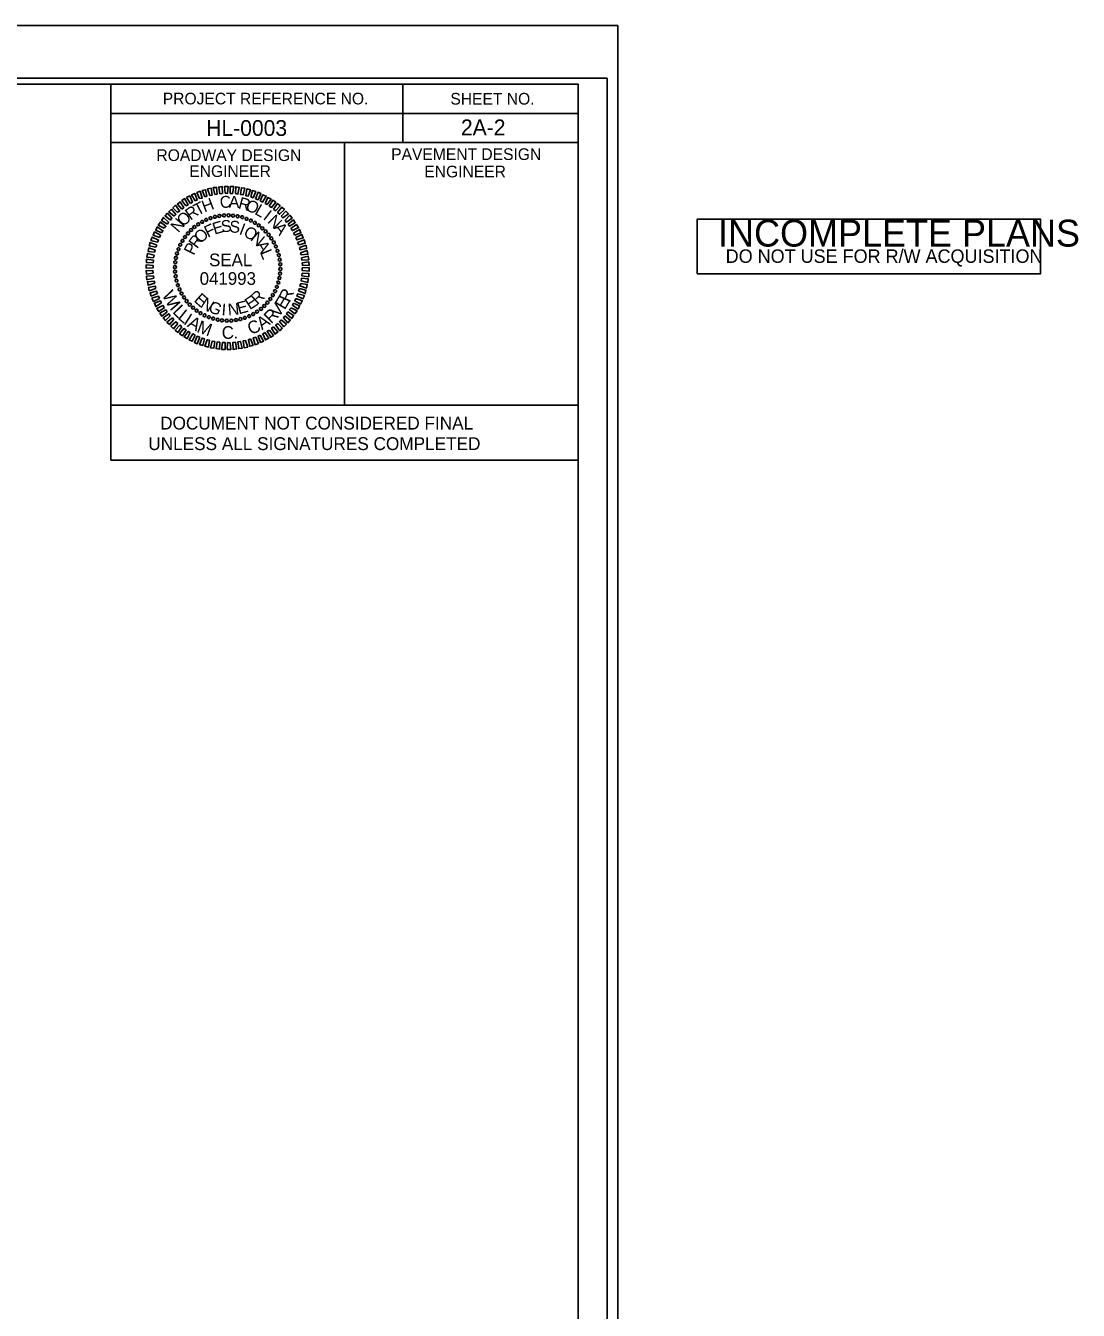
# Model space of a CAD drawing. Extents: x 1022283 to 1026986, y 174822 to 180471.
# Drawn here: x 1025859 to 1026986, y 176197 to 177572 of the extents above; entities that cross this region are included whole.
import ezdxf

# ---------------------------------------------------------------- set-up
doc = ezdxf.new("R2010")
doc.units = 0
for name, color, linetype in [('Default', 7, 'Continuous'), ('Sheet Cutting Line CELL', 7, 'Continuous'), ('Sheet Data Field CELL', 7, 'Continuous'), ('Sheet Plot Border Inside CELL', 7, 'Continuous'), ('Sheet Plot Border Outside CELL', 7, 'Continuous'), ('Sheet Sticker Exception Certification CELL', 7, 'Continuous'), ('Sheet Sticker Incomplete CELL', 7, 'Continuous'), ('Sheet Typical CELL', 7, 'Continuous')]:
    doc.layers.add(name, color=color, linetype=linetype)

msp = doc.modelspace()

# ---------------------------------------------------------------- linework, layer by layer
at = {"layer": 'Default'}
for p, q in [((1026048.2, 177362.5), (1026048.2, 177362.5)), ((1026052.6, 177364.8), (1026052.6, 177364.8)), ((1026057.1, 177366.6), (1026057.1, 177366.6)), ((1026061.8, 177367.9), (1026061.8, 177367.9)), ((1026066.8, 177368.8), (1026066.8, 177368.8)), ((1026071.6, 177369.5), (1026071.6, 177369.5)), ((1026076.6, 177369.6), (1026076.6, 177369.6)), ((1026081.5, 177369.3), (1026081.5, 177369.3)), ((1026086.3, 177368.5), (1026086.3, 177368.5)), ((1026091.1, 177367.5), (1026091.1, 177367.5)), ((1026095.8, 177365.9), (1026095.8, 177365.9)), ((1026100.3, 177363.9), (1026100.3, 177363.9)), ((1026104.7, 177361.6), (1026104.7, 177361.6)), ((1026032.9, 177350.2), (1026032.9, 177350.2)), ((1026036.3, 177353.7), (1026036.3, 177353.7)), ((1026040, 177357.1), (1026040, 177357.1)), ((1026043.9, 177359.9), (1026043.9, 177359.9)), ((1026108.7, 177358.8), (1026108.7, 177358.8)), ((1026112.7, 177355.8), (1026112.7, 177355.8)), ((1026116.2, 177352.4), (1026116.2, 177352.4)), ((1026119.5, 177348.7), (1026119.5, 177348.7)), ((1026024.8, 177337.9), (1026024.8, 177337.9)), ((1026027.1, 177342.3), (1026027.1, 177342.3)), ((1026029.9, 177346.3), (1026029.9, 177346.3)), ((1026122.3, 177344.7), (1026122.3, 177344.7)), ((1026124.9, 177340.5), (1026124.9, 177340.5)), ((1026127.2, 177336.1), (1026127.2, 177336.1)), ((1026020.2, 177323.9), (1026020.2, 177323.9)), ((1026021.2, 177328.6), (1026021.2, 177328.6)), ((1026022.8, 177333.4), (1026022.8, 177333.4)), ((1026129, 177331.6), (1026129, 177331.6)), ((1026130.3, 177326.8), (1026130.3, 177326.8)), ((1026131.2, 177321.9), (1026131.2, 177321.9)), ((1026019.1, 177314.1), (1026019.1, 177314.1)), ((1026019.2, 177309.2), (1026019.2, 177309.2)), ((1026019.4, 177319.1), (1026019.4, 177319.1)), ((1026075.5, 177313.1), (1026075.5, 177313.1)), ((1026131.7, 177307.2), (1026131.7, 177307.2)), ((1026131.9, 177317.1), (1026131.9, 177317.1)), ((1026132, 177312.1), (1026132, 177312.1)), ((1026019.9, 177304.3), (1026019.9, 177304.3)), ((1026020.8, 177299.4), (1026020.8, 177299.4)), ((1026022.1, 177294.7), (1026022.1, 177294.7)), ((1026128.3, 177292.9), (1026128.3, 177292.9)), ((1026129.9, 177297.6), (1026129.9, 177297.6)), ((1026130.9, 177302.3), (1026130.9, 177302.3)), ((1026023.9, 177290.2), (1026023.9, 177290.2)), ((1026026.2, 177285.8), (1026026.2, 177285.8)), ((1026028.7, 177281.5), (1026028.7, 177281.5)), ((1026121.2, 177279.9), (1026121.2, 177279.9)), ((1026124, 177284), (1026124, 177284)), ((1026126.3, 177288.4), (1026126.3, 177288.4)), ((1026031.6, 177277.6), (1026031.6, 177277.6)), ((1026034.9, 177273.9), (1026034.9, 177273.9)), ((1026038.4, 177270.5), (1026038.4, 177270.5)), ((1026042.4, 177267.4), (1026042.4, 177267.4)), ((1026107.2, 177266.3), (1026107.2, 177266.3)), ((1026111.1, 177269.1), (1026111.1, 177269.1)), ((1026114.8, 177272.5), (1026114.8, 177272.5)), ((1026118.2, 177276), (1026118.2, 177276)), ((1026046.4, 177264.6), (1026046.4, 177264.6)), ((1026050.8, 177262.4), (1026050.8, 177262.4)), ((1026055.3, 177260.4), (1026055.3, 177260.4)), ((1026060, 177258.8), (1026060, 177258.8)), ((1026064.7, 177257.8), (1026064.7, 177257.8)), ((1026069.6, 177257), (1026069.6, 177257)), ((1026074.5, 177256.6), (1026074.5, 177256.6)), ((1026079.5, 177256.8), (1026079.5, 177256.8)), ((1026084.3, 177257.4), (1026084.3, 177257.4)), ((1026089.3, 177258.3), (1026089.3, 177258.3)), ((1026094, 177259.7), (1026094, 177259.7)), ((1026098.5, 177261.5), (1026098.5, 177261.5)), ((1026102.9, 177263.7), (1026102.9, 177263.7))]:
    msp.add_line(p, q, dxfattribs=at)
for points in [[(1026035.7, 177382.3), (1026031.6, 177388.4), (1026035, 177390.2), (1026037.9, 177383.7)], [(1026040.6, 177385), (1026037, 177391.3), (1026040.4, 177392.9), (1026043, 177386)], [(1026045.5, 177387.4), (1026042.6, 177393.9), (1026046, 177395.2), (1026048.3, 177388)], [(1026051, 177389.2), (1026048.4, 177395.9), (1026051.9, 177396.9), (1026053.4, 177390)], [(1026056.4, 177390.6), (1026054.1, 177397.7), (1026057.9, 177398.5), (1026058.8, 177391.2)], [(1026061.8, 177391.9), (1026060, 177399.1), (1026063.7, 177399.4), (1026064.5, 177392.2)], [(1026067.2, 177392.5), (1026066, 177399.7), (1026069.8, 177400.2), (1026069.9, 177392.9)], [(1026072.8, 177393.1), (1026072.3, 177400.4), (1026076, 177400.3), (1026075.5, 177393)], [(1026078.2, 177393), (1026078.2, 177400.3), (1026082, 177400.2), (1026080.9, 177392.9)], [(1026083.9, 177392.7), (1026084.3, 177400), (1026088, 177399.3), (1026086.6, 177392.2)], [(1026089.3, 177391.8), (1026090.3, 177399), (1026094, 177398.4), (1026092, 177391.4)], [(1026095, 177390.5), (1026096.1, 177397.8), (1026100, 177396.9), (1026097.4, 177390)], [(1026100.4, 177389.1), (1026102.1, 177396), (1026105.6, 177394.9), (1026102.8, 177388.3)], [(1026105.5, 177387), (1026108.1, 177394.1), (1026111.2, 177392.8), (1026108.1, 177386.2)], [(1026110.5, 177384.9), (1026113.3, 177391.5), (1026116.8, 177390), (1026113, 177383.7)], [(1026018.3, 177368.7), (1026012.5, 177373.3), (1026015.4, 177375.9), (1026020.1, 177370.5)], [(1026022, 177372.6), (1026017, 177377.6), (1026019.7, 177380.3), (1026024.1, 177374.2)], [(1026026.5, 177376.1), (1026021.7, 177381.5), (1026024.7, 177383.9), (1026028.6, 177377.6)], [(1026030.8, 177379.5), (1026026.6, 177385.2), (1026029.5, 177387.4), (1026033.2, 177380.8)], [(1026115.7, 177382.3), (1026118.7, 177388.7), (1026122.1, 177386.8), (1026117.8, 177381)], [(1026120.1, 177379.3), (1026124, 177385.8), (1026127, 177383.4), (1026122.6, 177377.9)], [(1026124.7, 177375.9), (1026128.9, 177382.1), (1026131.8, 177379.6), (1026126.8, 177374.3)], [(1026129, 177372.4), (1026133.6, 177378.3), (1026136.3, 177375.6), (1026131.1, 177370.7)], [(1026007.6, 177355.6), (1026001.3, 177359), (1026003.5, 177362.2), (1026009.4, 177357.7)], [(1026011, 177360.1), (1026004.9, 177364), (1026007, 177367.2), (1026012.4, 177362.3)], [(1026014.3, 177364.4), (1026008.5, 177368.8), (1026011, 177371.7), (1026015.9, 177366.4)], [(1026133, 177368.5), (1026137.9, 177373.8), (1026140.6, 177371.1), (1026134.7, 177366.7)], [(1026137, 177364.4), (1026142.1, 177369.5), (1026144.5, 177366.4), (1026138.5, 177362.2)], [(1026140.3, 177360), (1026145.9, 177364.8), (1026148, 177361.5), (1026141.7, 177357.9)], [(1026002.6, 177345.6), (1025995.7, 177348.2), (1025997.4, 177351.7), (1026003.8, 177348.1)], [(1026004.9, 177350.8), (1025998.5, 177353.6), (1026000.2, 177357.1), (1026006.2, 177352.9)], [(1026143.3, 177355.4), (1026149.2, 177359.7), (1026151.4, 177356.3), (1026144.8, 177353.2)], [(1026146.2, 177350.5), (1026152.5, 177354.4), (1026154, 177350.9), (1026147.5, 177348.3)], [(1026148.4, 177345.6), (1026155.1, 177349), (1026156.5, 177345.4), (1026149.6, 177343.2)], [(1025997.2, 177329.9), (1025990.3, 177330.8), (1025991.1, 177334.6), (1025998.1, 177332.2)], [(1025998.7, 177335.3), (1025991.7, 177336.7), (1025992.5, 177340.5), (1025999.6, 177337.6)], [(1026000.4, 177340.7), (1025993.4, 177342.7), (1025994.9, 177346.2), (1026001.6, 177343)], [(1026150.5, 177340.3), (1026157.3, 177343.3), (1026158.6, 177339.8), (1026151.6, 177338)], [(1026152.3, 177334.9), (1026159.5, 177337.5), (1026160.1, 177333.8), (1026153.1, 177332.6)], [(1025995.8, 177318.7), (1025988.5, 177319), (1025988.7, 177322.7), (1025996, 177321.4)], [(1025996.3, 177324.1), (1025989.1, 177324.8), (1025989.6, 177328.6), (1025996.9, 177326.8)], [(1026153.6, 177329.5), (1026160.7, 177331.7), (1026161.4, 177327.9), (1026154.3, 177327.2)], [(1026154.6, 177324.1), (1026161.9, 177325.7), (1026162.3, 177321.9), (1026155.1, 177321.4)], [(1025995.8, 177307.5), (1025988.5, 177306.6), (1025988.2, 177310.4), (1025995.6, 177310.2)], [(1025995.7, 177313.1), (1025988.4, 177312.8), (1025988.4, 177316.6), (1025995.7, 177315.8)], [(1026155.3, 177307.5), (1026162.6, 177307.3), (1026162.4, 177303.6), (1026155.1, 177304.8)], [(1026155.3, 177318.7), (1026162.6, 177319.6), (1026162.8, 177315.8), (1026155.5, 177316)], [(1026155.4, 177313.1), (1026162.7, 177313.5), (1026162.7, 177309.6), (1026155.4, 177310.4)], [(1025996.5, 177302.1), (1025989.1, 177300.5), (1025988.8, 177304.3), (1025996, 177304.8)], [(1025997.5, 177296.7), (1025990.4, 177294.6), (1025989.7, 177298.4), (1025996.8, 177299.1)], [(1025998.8, 177291.3), (1025991.6, 177288.7), (1025990.9, 177292.4), (1025998, 177293.7)], [(1026153.8, 177296.4), (1026160.8, 177295.5), (1026160, 177291.6), (1026152.9, 177294)], [(1026154.7, 177302.1), (1026161.9, 177301.4), (1026161.5, 177297.6), (1026154.2, 177299.4)], [(1026000.6, 177285.9), (1025993.8, 177283), (1025992.5, 177286.5), (1025999.5, 177288.3)], [(1026002.6, 177280.6), (1025996, 177277.2), (1025994.5, 177280.8), (1026001.5, 177283.1)], [(1026148.4, 177280.6), (1026155.4, 177278), (1026153.7, 177274.5), (1026147.3, 177278.1)], [(1026150.7, 177285.6), (1026157.7, 177283.5), (1026156.2, 177280), (1026149.5, 177283.2)], [(1026152.4, 177291), (1026159.4, 177289.5), (1026158.6, 177285.8), (1026151.5, 177288.6)], [(1026004.9, 177275.8), (1025998.6, 177271.8), (1025997.1, 177275.3), (1026003.5, 177277.9)], [(1026007.8, 177270.8), (1026001.9, 177266.5), (1025999.7, 177269.9), (1026006.2, 177273.1)], [(1026010.7, 177266.2), (1026005.2, 177261.5), (1026003.1, 177264.7), (1026009.4, 177268.3)], [(1026140.1, 177266.1), (1026146.2, 177262.3), (1026144.1, 177259), (1026138.7, 177264)], [(1026143.5, 177270.6), (1026149.8, 177267.2), (1026147.5, 177264.1), (1026141.7, 177268.6)], [(1026146.2, 177275.4), (1026152.6, 177272.6), (1026150.9, 177269.1), (1026144.8, 177273.3)], [(1026014.1, 177261.8), (1026008.9, 177256.8), (1026006.6, 177259.8), (1026012.5, 177264.1)], [(1026018.1, 177257.8), (1026013.2, 177252.5), (1026010.5, 177255.2), (1026016.4, 177259.6)], [(1026022.1, 177253.8), (1026017.5, 177248), (1026014.8, 177250.7), (1026020, 177255.5)], [(1026026.4, 177250.3), (1026022.2, 177244.2), (1026019.3, 177246.6), (1026024.2, 177251.9)], [(1026129.1, 177253.6), (1026134, 177248.7), (1026131.3, 177246), (1026127, 177252)], [(1026132.8, 177257.5), (1026138.5, 177252.9), (1026135.7, 177250.3), (1026131, 177255.7)], [(1026136.7, 177261.8), (1026142.6, 177257.4), (1026140.1, 177254.5), (1026135.2, 177259.8)], [(1026031, 177247), (1026027.1, 177240.4), (1026024.1, 177242.8), (1026028.5, 177248.3)], [(1026035.4, 177243.9), (1026032.3, 177237.5), (1026029, 177239.4), (1026033.2, 177245.3)], [(1026040.6, 177241.3), (1026037.7, 177234.7), (1026034.3, 177236.3), (1026038.1, 177242.6)], [(1026045.6, 177239.2), (1026043, 177232.1), (1026039.9, 177233.5), (1026043, 177240)], [(1026050.7, 177237.2), (1026049, 177230.2), (1026045.5, 177231.3), (1026048.3, 177238)], [(1026105.6, 177238.9), (1026108.5, 177232.3), (1026105.1, 177231), (1026102.8, 177238.2)], [(1026110.5, 177241.2), (1026114.1, 177234.9), (1026110.6, 177233.4), (1026108.1, 177240.2)], [(1026115.4, 177243.9), (1026119.5, 177237.9), (1026116, 177236.1), (1026113.2, 177242.6)], [(1026120.3, 177246.7), (1026124.5, 177241), (1026121.6, 177238.9), (1026117.8, 177245.4)], [(1026124.6, 177250.1), (1026129.4, 177244.7), (1026126.4, 177242.4), (1026122.5, 177248.7)], [(1026056.1, 177235.7), (1026055, 177228.4), (1026051.1, 177229.3), (1026053.7, 177236.3)], [(1026061.8, 177234.5), (1026060.8, 177227.3), (1026057.1, 177227.8), (1026059.1, 177234.8)], [(1026067.2, 177233.6), (1026066.8, 177226.3), (1026063.1, 177226.9), (1026064.5, 177234)], [(1026072.8, 177233.2), (1026072.8, 177225.9), (1026069.1, 177226), (1026070.1, 177233.4)], [(1026078.2, 177233.1), (1026078.8, 177225.8), (1026075.1, 177225.9), (1026075.5, 177233.2)], [(1026083.9, 177233.7), (1026085.1, 177226.5), (1026081.3, 177226), (1026081.2, 177233.4)], [(1026089.3, 177234.4), (1026091.1, 177227.2), (1026087.4, 177226.8), (1026086.6, 177234)], [(1026094.7, 177235.6), (1026097, 177228.5), (1026093.2, 177227.7), (1026092.3, 177235)], [(1026100.1, 177237.1), (1026102.7, 177230.3), (1026099.2, 177229.3), (1026097.7, 177236.3)]]:
    msp.add_lwpolyline(points, close=True, dxfattribs=at)
for centre, major_axis in [((1026044, 177359.9), (-0.91, 1.34)), ((1026048.2, 177362.5), (-0.79, 1.42)), ((1026052.6, 177364.7), (-0.66, 1.48)), ((1026057.2, 177366.5), (-0.53, 1.53)), ((1026061.9, 177367.9), (-0.39, 1.57)), ((1026066.7, 177368.9), (-0.25, 1.6)), ((1026071.6, 177369.4), (-0.11, 1.62)), ((1026076.5, 177369.5), (0.03, 1.62)), ((1026081.4, 177369.2), (0.17, 1.61)), ((1026086.3, 177368.5), (0.31, 1.59)), ((1026091.1, 177367.4), (0.45, 1.56)), ((1026095.8, 177365.8), (0.58, 1.51)), ((1026100.3, 177363.8), (0.71, 1.46)), ((1026104.6, 177361.5), (0.83, 1.39)), ((1026029.9, 177346.3), (-1.31, 0.95)), ((1026033, 177350.1), (-1.22, 1.06)), ((1026036.3, 177353.7), (-1.13, 1.17)), ((1026040, 177357), (-1.02, 1.26)), ((1026108.7, 177358.8), (0.95, 1.31)), ((1026112.6, 177355.7), (1.06, 1.22)), ((1026116.1, 177352.3), (1.17, 1.13)), ((1026119.4, 177348.6), (1.26, 1.02)), ((1026022.9, 177333.3), (-1.51, 0.58)), ((1026024.8, 177337.9), (-1.46, 0.71)), ((1026027.2, 177342.2), (-1.39, 0.83)), ((1026122.3, 177344.7), (1.34, 0.91)), ((1026124.9, 177340.5), (1.42, 0.79)), ((1026127.1, 177336.1), (1.48, 0.66)), ((1026019.4, 177319), (-1.61, 0.17)), ((1026020.1, 177323.9), (-1.59, 0.31)), ((1026021.3, 177328.7), (-1.56, 0.45)), ((1026128.9, 177331.5), (1.53, 0.53)), ((1026130.3, 177326.8), (1.57, 0.39)), ((1026131.3, 177321.9), (1.6, 0.25)), ((1026019.1, 177314.1), (-1.62, 0.03)), ((1026019.2, 177309.2), (-1.62, -0.11)), ((1026131.7, 177307.2), (1.61, -0.17)), ((1026131.8, 177317.1), (1.62, 0.11)), ((1026132, 177312.1), (1.62, -0.03)), ((1026019.8, 177304.3), (-1.6, -0.25)), ((1026020.8, 177299.5), (-1.57, -0.39)), ((1026022.2, 177294.7), (-1.53, -0.53)), ((1026128.2, 177292.9), (1.51, -0.58)), ((1026129.8, 177297.6), (1.56, -0.45)), ((1026130.9, 177302.4), (1.59, -0.31)), ((1026024, 177290.2), (-1.48, -0.66)), ((1026026.2, 177285.8), (-1.42, -0.79)), ((1026028.8, 177281.6), (-1.34, -0.91)), ((1026031.7, 177277.6), (-1.26, -1.02)), ((1026121.2, 177279.9), (1.31, -0.95)), ((1026123.9, 177284.1), (1.39, -0.83)), ((1026126.3, 177288.4), (1.46, -0.71)), ((1026034.9, 177273.9), (-1.17, -1.13)), ((1026038.5, 177270.5), (-1.06, -1.22)), ((1026042.4, 177267.5), (-0.95, -1.31)), ((1026046.5, 177264.7), (-0.83, -1.39)), ((1026102.9, 177263.8), (0.79, -1.42)), ((1026107.1, 177266.3), (0.91, -1.34)), ((1026111.1, 177269.3), (1.02, -1.26)), ((1026114.7, 177272.5), (1.13, -1.17)), ((1026118.1, 177276.1), (1.22, -1.06)), ((1026050.8, 177262.4), (-0.71, -1.46)), ((1026055.3, 177260.4), (-0.58, -1.51)), ((1026060, 177258.9), (-0.45, -1.56)), ((1026064.8, 177257.7), (-0.31, -1.59)), ((1026069.6, 177257), (-0.17, -1.61)), ((1026074.6, 177256.7), (-0.03, -1.62)), ((1026079.5, 177256.8), (0.11, -1.62)), ((1026084.4, 177257.4), (0.25, -1.6)), ((1026089.2, 177258.4), (0.39, -1.57)), ((1026093.9, 177259.8), (0.53, -1.53)), ((1026098.5, 177261.6), (0.66, -1.48))]:
    msp.add_ellipse(centre, major_axis=major_axis, ratio=0.999708, dxfattribs=at)
at = {"layer": 'Sheet Cutting Line CELL'}
msp.add_line((1026493.2, 177572.5), (1022283.2, 177572.5), dxfattribs=at)
at = {"layer": 'Sheet Plot Border Inside CELL'}
msp.add_lwpolyline([(1026482, 177516.3), (1022315.7, 177516.3), (1022315.7, 174878.6), (1026482, 174878.6)], close=True, dxfattribs=at)
at = {"layer": 'Sheet Plot Border Outside CELL'}
msp.add_lwpolyline([(1026493.2, 177572.5), (1022283.2, 177572.5), (1022283.2, 174822.5), (1026493.2, 174822.5)], close=True, dxfattribs=at)
at = {"layer": 'Sheet Sticker Exception Certification CELL'}
for p, q in [((1025950.6, 177107.3), (1025950.6, 177166.1)), ((1025950.6, 177166.1), (1026450.7, 177166.1)), ((1026450.7, 177166), (1026450.7, 177107.3)), ((1026450.7, 177107.3), (1025950.6, 177107.3))]:
    msp.add_line(p, q, dxfattribs=at)
at = {"layer": 'Sheet Sticker Incomplete CELL'}
msp.add_lwpolyline([(1026578.2, 177306.7), (1026578.2, 177365.5), (1026945.7, 177365.5), (1026945.7, 177306.7)], close=True, dxfattribs=at)
at = {"layer": 'Sheet Typical CELL'}
for p, q in [((1026263.2, 177509.8), (1026263.2, 177447.3)), ((1025950.6, 177478.6), (1026450.7, 177478.6)), ((1026200.7, 177447.3), (1026200.7, 177166.2))]:
    msp.add_line(p, q, dxfattribs=at)
for points in [[(1026450.7, 177510), (1022700.7, 177510), (1022700.7, 174885), (1026450.7, 174885)], [(1025950.6, 177510), (1026450.7, 177510), (1026450.7, 177447.3), (1025950.6, 177447.3)], [(1025950.6, 177447.3), (1026200.7, 177447.3), (1026200.7, 177166.1), (1025950.6, 177166.1)], [(1026200.7, 177447.3), (1026450.7, 177447.3), (1026450.7, 177166.1), (1026200.7, 177166.1)]]:
    msp.add_lwpolyline(points, close=True, dxfattribs=at)

# ---------------------------------------------------------------- texts
at = {"layer": 'Default'}
for s, height, rotation, p in [('C', 12.7, 6.2199, (1026067.8, 177376.9)), ('A', 12.7, 359.0203, (1026076.7, 177377.6)), ('R', 12.7, 344.6211, (1026086.1, 177377.1)), ('R', 12.7, 35.0205, (1026035.7, 177363.7)), ('T', 12.7, 27.8198, (1026043.4, 177368.7)), ('H', 12.7, 20.6195, (1026050.7, 177372.4)), ('O', 12.7, 337.4212, (1026093.7, 177375.4)), ('L', 12.7, 330.2209, (1026103.6, 177371.3)), ('I', 12.7, 323.0201, (1026112.7, 177365.9)), ('N', 12.7, 49.4235, (1026022.8, 177350.2)), ('O', 12.7, 42.2217, (1026028, 177356.8)), ('E', 12.7, 16.6111, (1026061.5, 177348.7)), ('S', 12.7, 7.2556, (1026069.2, 177351)), ('S', 12.7, 357.9004, (1026077.3, 177351.1)), ('N', 12.7, 315.8189, (1026117.5, 177362.4)), ('R', 12.7, 54.0397, (1026042.9, 177333.1)), ('O', 12.7, 44.6812, (1026046.9, 177338.7)), ('F', 12.7, 25.967, (1026054.3, 177345.3)), ('I', 12.7, 339.1896, (1026087, 177349.6)), ('O', 12.7, 329.8335, (1026091.5, 177348)), ('N', 12.7, 320.4766, (1026099.1, 177343.5)), ('A', 12.7, 308.6172, (1026124.1, 177355.8)), ('P', 12.7, 63.3989, (1026039.3, 177325.9)), ('A', 12.7, 301.7603, (1026105.5, 177337.6)), ('SEAL', 13.5, 360, (1026055.7, 177315)), ('L', 12.7, 292.4008, (1026109.9, 177329.9)), ('W', 13.5, 298.3574, (1026004.9, 177284.4)), ('E', 12.7, 318.2769, (1026038.6, 177277.9)), ('N', 12.7, 327.634, (1026045.4, 177271.8)), ('E', 12.7, 33.1241, (1026099.3, 177267.9)), ('R', 12.7, 42.4814, (1026107.3, 177273.2)), ('E', 13.5, 59.5871, (1026136.7, 177267.6)), ('R', 13.5, 66.6964, (1026141.9, 177275.5)), ('I', 13.5, 310.8915, (1026012.8, 177269.8)), ('L', 13.5, 314.6934, (1026015.8, 177265.7)), ('L', 13.5, 320.9682, (1026021.3, 177259.4)), ('G', 12.7, 336.9902, (1026053.9, 177266.8)), ('I', 12.7, 355.7012, (1026068.7, 177262.5)), ('N', 12.7, 5.0564, (1026076.2, 177262.2)), ('E', 12.7, 14.4118, (1026087.4, 177263.5)), ('R', 13.5, 43.8538, (1026122.1, 177252.7)), ('V', 13.5, 51.3341, (1026129.6, 177259.3)), ('I', 13.5, 327.2429, (1026027.5, 177253.8)), ('A', 13.5, 331.0449, (1026031.6, 177250.8)), ('M', 13.5, 339.8852, (1026041.7, 177244.8)), ('C', 13.5, 25.4313, (1026100.6, 177241.1)), ('A', 13.5, 35.0135, (1026112.3, 177246.3)), ('C', 13.5, 1.6151, (1026069.4, 177237.1)), ('.', 13.5, 11.1972, (1026082.1, 177237.1))]:
    msp.add_text(s, height=height, rotation=rotation, dxfattribs=at).set_placement(p)
msp.add_text('041993', height=13.5, dxfattribs=at).set_placement((1026045.6, 177295.1))
at = {"layer": 'Sheet Data Field CELL'}
for s, p in [('HL-0003', (1026052.6, 177454.5)), ('2A-2', (1026325.3, 177455.2))]:
    msp.add_text(s, height=16.88, dxfattribs=at).set_placement(p)
at = {"layer": 'Sheet Sticker Exception Certification CELL'}
for s, p in [('DOCUMENT NOT CONSIDERED FINAL', (1026003.3, 177140.2)), ('UNLESS ALL SIGNATURES COMPLETED', (1025990.6, 177118.2))]:
    msp.add_text(s, height=13.75, dxfattribs=at).set_placement(p)
at = {"layer": 'Sheet Sticker Incomplete CELL'}
for s, height, p in [('INCOMPLETE PLANS', 28.8, (1026600.6, 177336)), ('DO NOT USE FOR R/W ACQUISITION', 14.4, (1026608.7, 177318.6))]:
    msp.add_text(s, height=height, dxfattribs=at).set_placement(p)
at = {"layer": 'Sheet Typical CELL'}
for s, p in [('PROJECT REFERENCE NO.', (1026006.1, 177488.2)), ('SHEET NO.', (1026314, 177488)), ('ROADWAY DESIGN', (1025999.3, 177427.6)), ('PAVEMENT DESIGN', (1026250.6, 177428.7)), ('ENGINEER', (1026034.5, 177410.5)), ('ENGINEER', (1026286.1, 177410.1))]:
    msp.add_text(s, height=12.5, dxfattribs=at).set_placement(p)

doc.saveas('drawing.dxf')
